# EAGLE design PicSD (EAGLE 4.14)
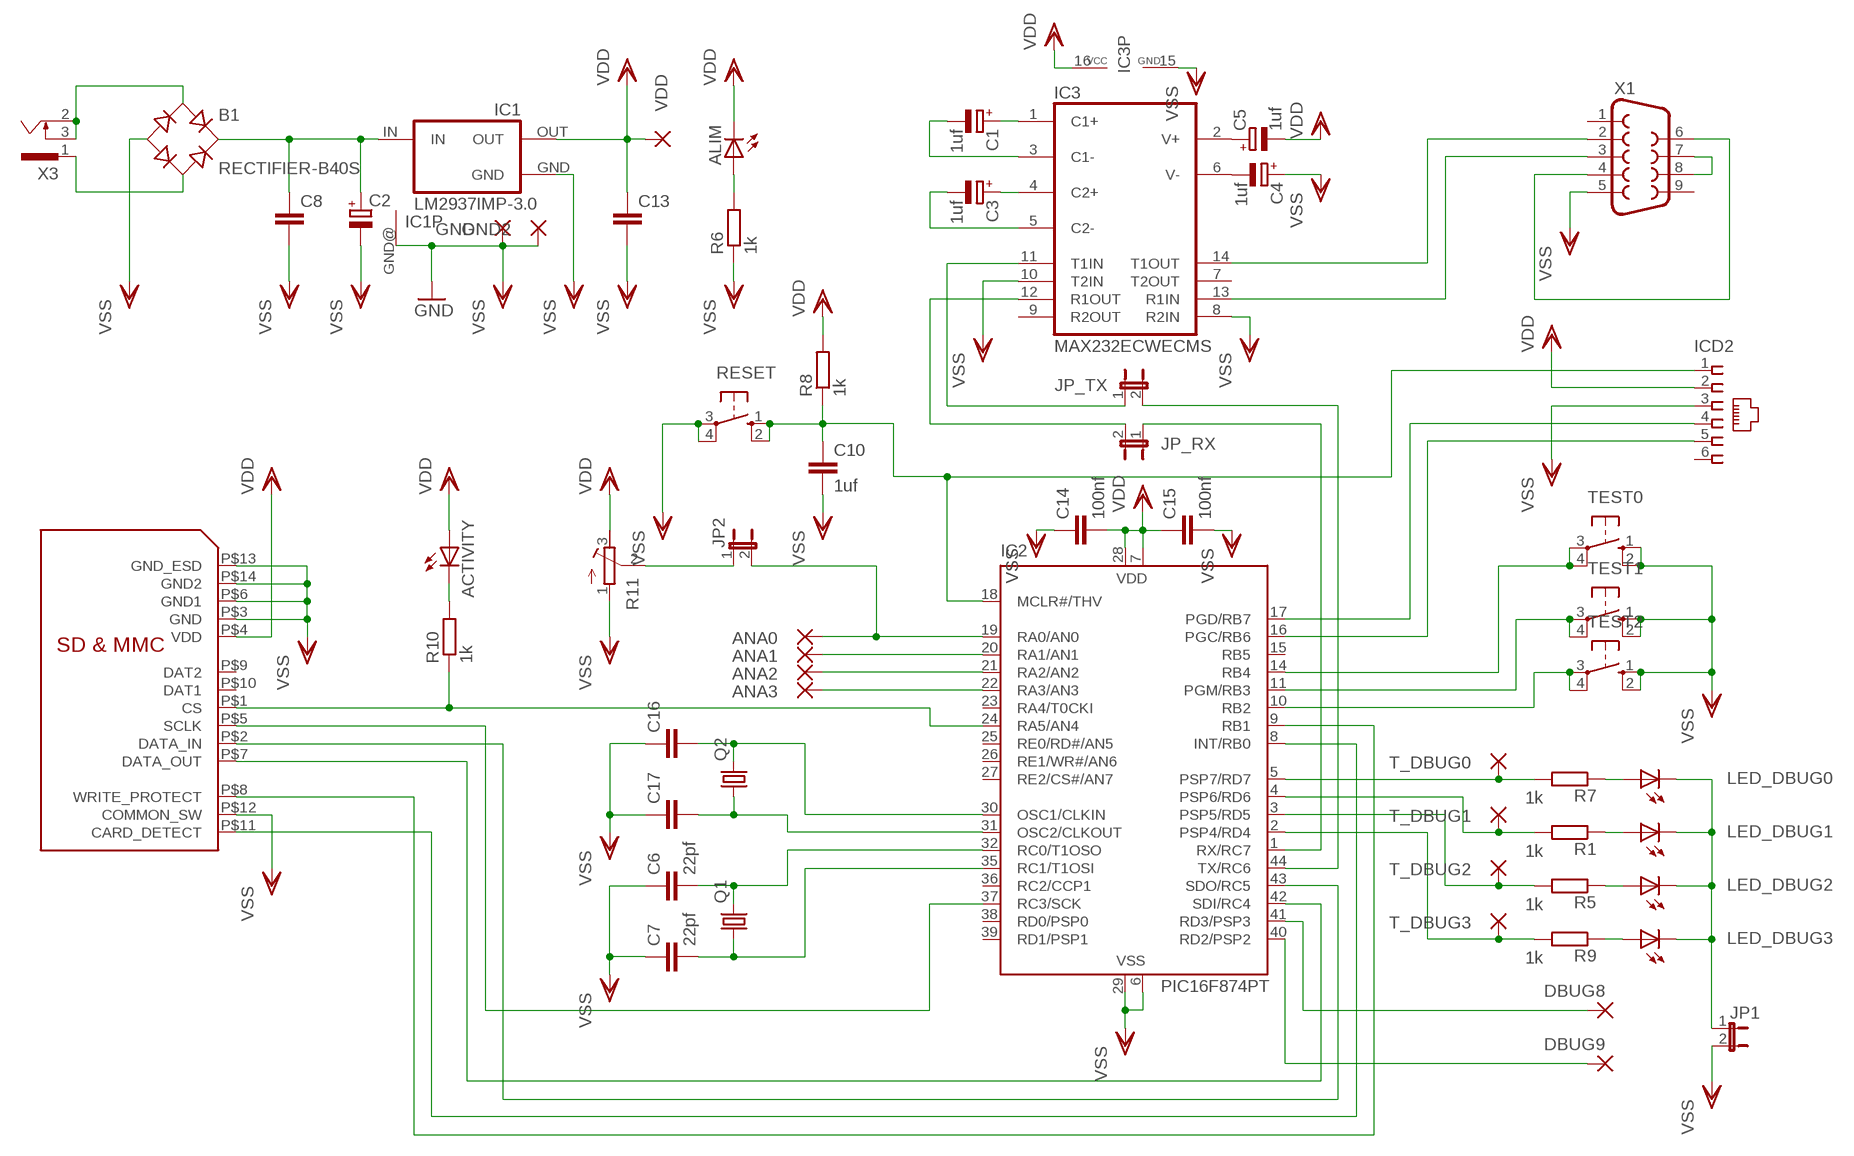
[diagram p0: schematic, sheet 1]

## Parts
ACTIVITY  LEDSMT1206  [1206]
ALIM  LEDSMT1206  [1206]
ANA0  3,81/1,1  [3,81/1,1]
ANA1  3,81/1,1  [3,81/1,1]
ANA2  3,81/1,1  [3,81/1,1]
ANA3  3,81/1,1  [3,81/1,1]
B1  RECTIFIER-B40S  [B40S]
C1  1uf  CPOL-EUB  [PANASONIC_B]
C2  CPOL-EUB  [PANASONIC_B]
C3  1uf  CPOL-EUB  [PANASONIC_B]
C4  1uf  CPOL-EUB  [PANASONIC_B]
C5  1uf  CPOL-EUB  [PANASONIC_B]
C6  22pf  C-EUC0805  [C0805]
C7  22pf  C-EUC0805  [C0805]
C8  C-EUC0805  [C0805]
C10  1uf  C-EUC0805  [C0805]
C13  C-EUC0805  [C0805]
C14  100nf  C-EUC0805  [C0805]
C15  100nf  C-EUC0805  [C0805]
C16  C-EUC0805  [C0805]
C17  C-EUC0805  [C0805]
DBUG8  3,81/1,1  [3,81/1,1]
DBUG9  3,81/1,1  [3,81/1,1]
GND  3,81/1,1  [3,81/1,1]
GND2  3,81/1,1  [3,81/1,1]
IC1  LM2937IMP-3.0  LM2937IMP-5.0  [SOT223]
IC2  PIC16F874PT  [TQFP44]
IC3  MAX232ECWECMS  [SO16]
ICD2  520250-3  [520250-3]
JP1  JP1E  [JP1]
JP2  JP1E  [JP1]
JP_RX  JP1E  [JP1]
JP_TX  JP1E  [JP1]
LED_DBUG0  LEDSMT1206  [1206]
LED_DBUG1  LEDSMT1206  [1206]
LED_DBUG2  LEDSMT1206  [1206]
LED_DBUG3  LEDSMT1206  [1206]
Q1  CRYTALTC26H  [TC26H]
Q2  CRYTALSM49  [SM49]
R1  1k  R-EU_R0805  [R0805]
R5  1k  R-EU_R0805  [R0805]
R6  1k  R-EU_R0805  [R0805]
R7  1k  R-EU_R0805  [R0805]
R8  1k  R-EU_R0805  [R0805]
R9  1k  R-EU_R0805  [R0805]
R10  1k  R-EU_R0805  [R0805]
R11  R-TRIMM3339P  [RTRIM3339P]
RESET  10-XX  [B3F-10XX]
SD1  FPS009-2405-0  FPS009-2405-0"  [FPS009-2405]
T_DBUG0  3,81/1,1  [3,81/1,1]
T_DBUG1  3,81/1,1  [3,81/1,1]
T_DBUG2  3,81/1,1  [3,81/1,1]
T_DBUG3  3,81/1,1  [3,81/1,1]
TEST0  10-XX  [B3F-10XX]
TEST1  10-XX  [B3F-10XX]
TEST2  10-XX  [B3F-10XX]
VDD  3,81/1,1  [3,81/1,1]
X1  F09H  [F09H]
X3  SCD-014A  [SCD-014-A]

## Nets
-SS: IC2.24(RA5/AN4) R10.1 SD1.P$1(CS)
N$1: C5.+ IC3.2(V+)
N$2: C4.- IC3.6(V-)
N$3: ALIM.A R6.2
N$4: ACTIVITY.C R10.2
N$5: IC2.9(RB1) SD1.P$8(WRITE_PROTECT)
N$7: ANA0.1(P) IC2.19(RA0/AN0) JP2.2
N$8: ANA1.1(P) IC2.20(RA1/AN1)
N$10: ANA2.1(P) IC2.21(RA2/AN2)
N$11: ANA3.1(P) IC2.22(RA3/AN3)
N$12: IC2.11(PGM/RB3) TEST1.3(P) TEST1.4(P1)
N$13: IC2.8(INT/RB0) SD1.P$11(CARD_DETECT)
N$14: IC2.10(RB2) TEST2.3(P) TEST2.4(P1)
N$15: IC2.14(RB4) TEST0.3(P) TEST0.4(P1)
N$16: IC2.5(PSP7/RD7) R7.2 T_DBUG0.1(P)
N$17: IC2.4(PSP6/RD6) R1.2 T_DBUG1.1(P)
N$18: IC2.3(PSP5/RD5) R5.2 T_DBUG2.1(P)
N$19: LED_DBUG0.A R7.1
N$20: LED_DBUG1.A R1.1
N$21: LED_DBUG2.A R5.1
N$22: C16.2 IC2.30(OSC1/CLKIN) Q2.2
N$24: DBUG8.1(P) IC2.41(RD3/PSP3)
N$25: C1.+ IC3.1(C1+)
N$26: C10.1 IC2.18(MCLR#/THV) ICD2.1 R8.1 RESET.1(S) RESET.2(S1)
N$27: DBUG9.1(P) IC2.40(RD2/PSP2)
N$28: C6.2 IC2.32(RC0/T1OSO) Q1.2
N$29: C7.2 IC2.35(RC1/T1OSI) Q1.1
N$30: B1.+ C2.+ C8.1 IC1.IN
N$31: B1.AC1 X3.2 X3.3
N$32: B1.AC2 X3.1
N$33: X1.7 X1.8
N$34: JP1.1 LED_DBUG0.C LED_DBUG1.C LED_DBUG2.C LED_DBUG3.C
N$35: LED_DBUG3.A R9.1
N$36: C1.- IC3.3(C1-)
N$37: C3.- IC3.5(C2-)
N$38: IC2.2(PSP4/RD4) R9.2 T_DBUG3.1(P)
N$39: C3.+ IC3.4(C2+)
N$41: JP2.1 R11.2(S)
N$42: IC3.14(T1OUT) X1.2
N$44: IC3.13(R1IN) X1.3
N$45: X1.4 X1.6
N$51: IC3.12(R1OUT) JP_RX.2
N$52: IC3.11(T1IN) JP_TX.1
N$69: C17.2 IC2.31(OSC2/CLKOUT) Q2.1
RB6: IC2.16(PGC/RB6) ICD2.5
RB7: IC2.17(PGD/RB7) ICD2.4
RC6: IC2.44(TX/RC6) JP_TX.2
RC7: IC2.1(RX/RC7) JP_RX.1
SCK: IC2.37(RC3/SCK) SD1.P$5(SCLK)
SDI: IC2.42(SDI/RC4) SD1.P$7(DATA_OUT)
SDO: IC2.43(SDO/RC5) SD1.P$2(DATA_IN)
VDD: ACTIVITY.A ALIM.C C5.- C13.1 C14.2 C15.1 IC1.OUT IC2.7(VDD) IC2.28(VDD) IC3.16(VCC) ICD2.2 R8.2 R11.3(A) SD1.P$4(VDD) VDD.1(P)
VSS: B1.- C2.- C4.+ C6.1 C7.1 C8.2 C10.2 C13.2 C14.1 C15.2 C16.1 C17.1 GND2.1(P) GND.1(P) IC1.GND IC1.GND@(GND) IC2.6(VSS) IC2.29(VSS) IC3.8(R2IN) IC3.10(T2IN) IC3.15(GND) ICD2.3 JP1.2 R6.1 R11.1(E) RESET.3(P) RESET.4(P1) SD1.P$3(GND) SD1.P$6(GND1) SD1.P$12(COMMON_SW) SD1.P$13(GND_ESD) SD1.P$14(GND2) TEST0.1(S) TEST0.2(S1) TEST1.1(S) TEST1.2(S1) TEST2.1(S) TEST2.2(S1) X1.5 ; supply symbol labelled GND
Unconnected: IC2.15(RB5) IC2.23(RA4/T0CKI) IC2.25(RE0/RD#/AN5) IC2.26(RE1/WR#/AN6) IC2.27(RE2/CS#/AN7) IC2.36(RC2/CCP1) IC2.38(RD0/PSP0) IC2.39(RD1/PSP1) IC3.7(T2OUT) IC3.9(R2OUT) ICD2.6 SD1.P$9(DAT2) SD1.P$10(DAT1) X1.1 X1.9

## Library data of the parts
ACTIVITY ALIM LED_DBUG0 LED_DBUG1-LED_DBUG3 = led:LED: LED
ANA0 ANA1-ANA3 DBUG8 DBUG9 GND GND2 T_DBUG0 T_DBUG1-T_DBUG3 VDD = wirepad:3,81/1,1: THROUGH-HOLE PAD
B1 = rectifier:RECTIFIER-: Rectifier
C1-C5 = rcl:CPOL-EU: POLARIZED CAPACITOR, European symbol
C6-C8 C10 C13-C17 = rcl:C-EU: CAPACITOR, European symbol
IC1 = lm2937:LM2937IMP-*: 400 and 500 mA Low Dropout Voltage Regulator NATIONAL SEMICONDUCTOR created by Peter.Hofmann@ph-tronic.de 10-2004 Rev.0
IC2 = microchip:PIC16F87*: MICROCONTROLLER
IC3 = maxim:MAX232ECWE: RS232 TRANSEIVER
ICD2 = con-amp:520250-3: AMP connector
JP1 JP2 JP_RX JP_TX = jumper:JP1E: JUMPER
Q1 Q2 = crystal:CRYTAL: CRYSTAL
R1 R5-R10 = rcl:R-EU_: RESISTOR, European symbol
R11 = rcl:R-TRIMM: Trimm resistor
RESET TEST0 TEST1 TEST2 = switch-omron:10-XX: OMRON SWITCH
SD1 = con-yamaichi-sd:FPS009-2405-0
X1 = con-subd:F09: SUB-D
X3 = con-shiua-chyuan:SCD-014A: Power Jack 2.5mm

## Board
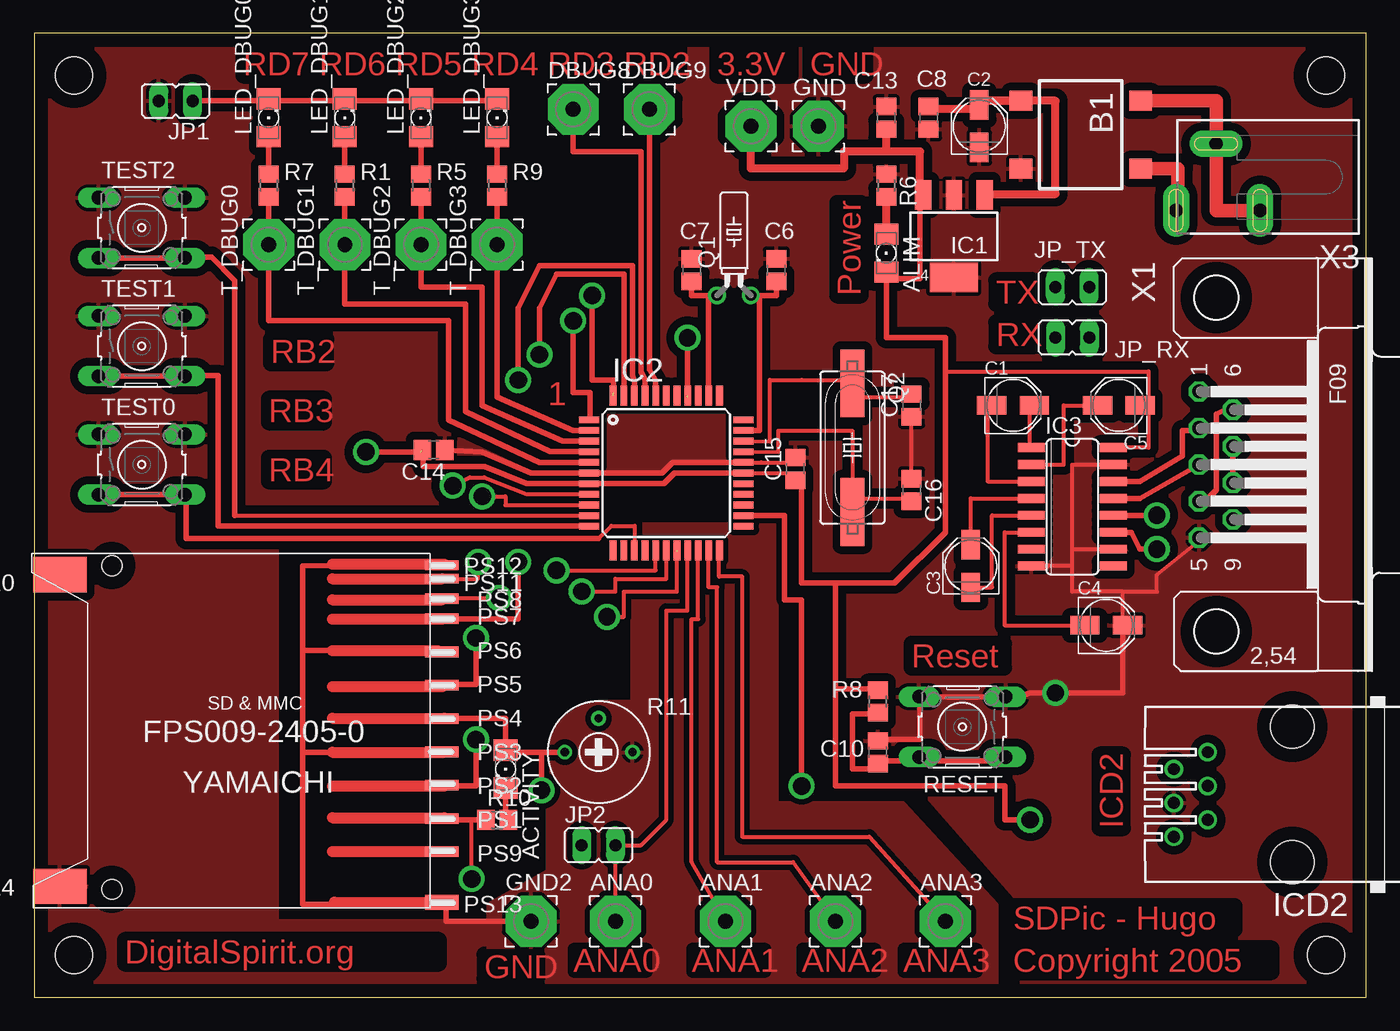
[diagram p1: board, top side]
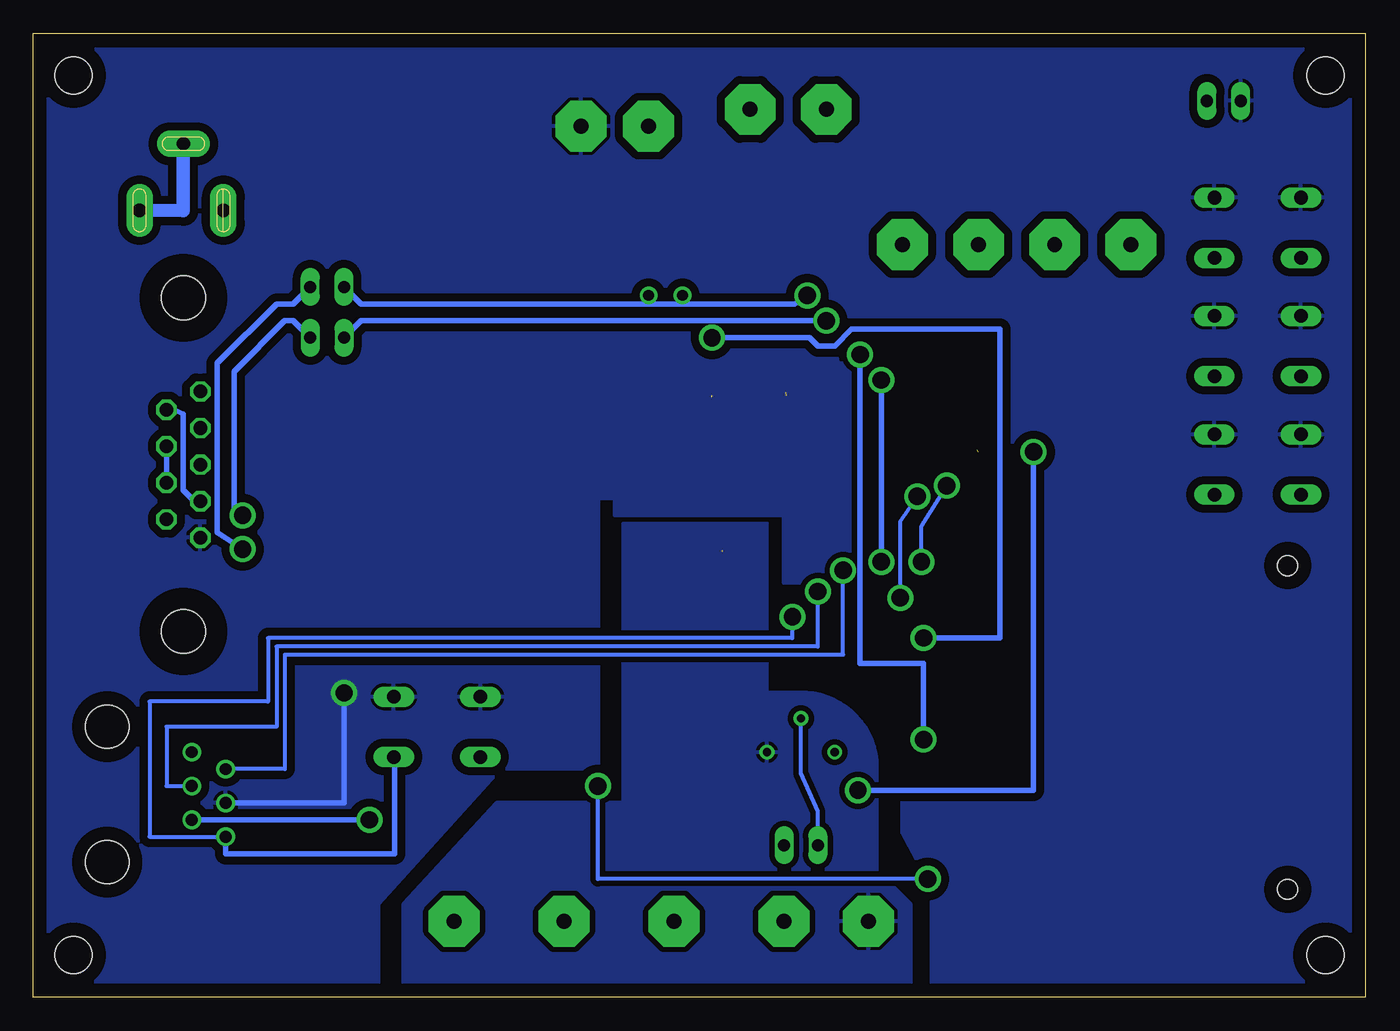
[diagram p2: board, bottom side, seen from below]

Size 100 x 72.38 mm. Coordinates in mm from the lower left corner, seen from the top.
Outline: 0,0 100,0 100,72.38 0,72.38 0,0
Copper layers (1*16): Top 0.035mm / dielectric 1.5mm / Bottom 0.035mm
Design rules "default": minimum track width 10mil, minimum drill 24mil, track to track 8mil, track to pad 8mil, pad to pad 8mil, via to via 8mil, smd to smd 8mil, copper to edge 40mil, drill to drill 8mil, minimum pad ring 10mil, minimum via ring 8mil, stop-mask expansion 4mil, vias tented up to drill 0mil, thermal gap 10mil
Holes 2.8 mm at 3.01,69.21 3.01,3.17 96.99,3.17 96.99,69.21

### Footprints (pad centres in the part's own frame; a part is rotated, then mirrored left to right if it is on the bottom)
1206 = smd 1.6 x 1.803: A -1.422,0; C 1.422,0
3,81/1,1 = drill 1.118 pad 3.81 octagon: 1 0,0
B40S = smd 1.5 x 1.7: + -2.55,-4.5; - 2.55,-4.5; AC1 -2.55,4.5; AC2 2.55,4.5
PANASONIC_B = smd 2.2 x 1.4: + 1.6,0; - -1.6,0
C0805 = smd 1.3 x 1.5: 1 -0.85,0; 2 0.85,0
SOT223 = smd 1.219 x 2.235: GND 0,-3.099; IN -2.311,-3.099; OUT 2.311,-3.099 | smd 3.6 x 2.2: GND@ 0,3.099
TQFP44 = smd 1.5 x 0.5: 1 -5.8,4; 2 -5.8,3.2; 3 -5.8,2.4; 4 -5.8,1.6; 5 -5.8,0.8; 6 -5.8,0; 7 -5.8,-0.8; 8 -5.8,-1.6; 9 -5.8,-2.4; 10 -5.8,-3.2; 11 -5.8,-4; 23 5.8,-4; 24 5.8,-3.2; 25 5.8,-2.4; 26 5.8,-1.6; 27 5.8,-0.8; 28 5.8,0; 29 5.8,0.8; 30 5.8,1.6; 31 5.8,2.4; 32 5.8,3.2; 33 5.8,4 | smd 0.5 x 1.5: 12 -4,-5.8; 13 -3.2,-5.8; 14 -2.4,-5.8; 15 -1.6,-5.8; 16 -0.8,-5.8; 17 0,-5.8; 18 0.8,-5.8; 19 1.6,-5.8; 20 2.4,-5.8; 21 3.2,-5.8; 22 4,-5.8; 34 4,5.8; 35 3.2,5.8; 36 2.4,5.8; 37 1.6,5.8; 38 0.8,5.8; 39 0,5.8; 40 -0.8,5.8; 41 -1.6,5.8; 42 -2.4,5.8; 43 -3.2,5.8; 44 -4,5.8
SO16 = smd 0.66 x 2.032: 1 -4.445,-3.073; 2 -3.175,-3.073; 3 -1.905,-3.073; 4 -0.635,-3.073; 5 0.635,-3.073; 6 1.905,-3.073; 7 3.175,-3.073; 8 4.445,-3.073; 9 4.445,3.073; 10 3.175,3.073; 11 1.905,3.073; 12 0.635,3.073; 13 -0.635,3.073; 14 -1.905,3.073; 15 -3.175,3.073; 16 -4.445,3.073
520250-3 = drill 0.889 round: 1 -3.175,8.89; 2 -1.905,6.35; 3 -0.635,8.89; 4 0.635,6.35; 5 1.905,8.89; 6 3.175,6.35 | hole 3.251: -5.08,0; 5.08,0
JP1 = drill 0.914 long: 1 0,-1.27; 2 0,1.27
TC26H = drill 0.813 round: 1 -1.27,0; 2 1.27,0
SM49 = smd 5.08 x 1.778: 1 -4.826,0; 2 4.826,0
R0805 = smd 1.3 x 1.5: 1 -0.85,0; 2 0.85,0
RTRIM3339P = drill 0.61 round: 1 -2.54,0; 2 0,-2.54; 3 2.54,0
B3F-10XX = drill 1.016 long: 1 -3.251,2.261; 2 3.251,2.261; 3 -3.251,-2.261; 4 3.251,-2.261
FPS009-2405 = smd 2.5 x 0.8: P$1 -14.27,6.88; P$2 -14.27,4.38; P$3 -14.27,1.88; P$4 -14.27,-0.62; P$5 -14.27,-3.12; P$6 -14.27,-5.62; P$7 -14.27,-8.12; P$8 -14.27,-9.62; P$9 -14.27,9.38 | smd 4 x 2.65: P$10 14.4,-11.42; P$14 14.4,11.98 | smd 2.5 x 0.7: P$11 -14.27,-11.12; P$12 -14.27,-12.12 | smd 2.5 x 1.1: P$13 -14.27,13.18 | hole 1.5: 10.5,12.2; 10.5,-12.1
F09H = drill 1.016 octagon: 1 -5.486,-1.27; 2 -2.743,-1.27; 3 0,-1.27; 4 2.743,-1.27; 5 5.486,-1.27; 6 -4.115,1.27; 7 -1.372,1.27; 8 1.372,1.27; 9 4.115,1.27 | hole 3.302: -12.522,0; 12.522,0
SCD-014-A = drill 1 pad 2 long: 1 -2.5,13.8; 2 -2.5,7.5; 3 2.5,10.8

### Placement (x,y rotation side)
ACTIVITY  35.39,17.14 270 top
ALIM  63.97,55.88 270 top
ANA0  43.65,5.71 0 top
ANA1  51.91,5.71 0 top
ANA2  60.16,5.71 0 top
ANA3  68.41,5.71 0 top
B1  78.58,64.77 270 top
C1  73.5,44.45 0 top
C2  70.95,65.4 90 top
C3  70.32,32.38 90 top
C4  80.48,27.93 0 top
C5  81.43,44.45 180 top
C6  55.71,54.61 270 top
C7  49.37,54.61 270 top
C8  67.14,66.03 270 top
C10  63.34,18.41 90 top
C13  63.97,66.03 90 top
C14  30,41.11 180 top
C15  57.14,39.68 90 top
C16  65.88,38.1 270 top
C17  65.88,44.45 90 top
DBUG8  40.48,66.67 0 top
DBUG9  46.19,66.67 0 top
GND  58.89,65.4 0 top
GND2  37.3,5.71 0 top
IC1  69.05,57.15 180 top
IC2  47.46,39.37 0 top
IC3  77.94,36.83 270 top
ICD2  94.45,15.24 90 top
JP1  10.63,67.3 90 top
JP2  42.38,11.43 270 top
JP_RX  77.94,49.53 270 top
JP_TX  77.94,53.34 90 top
LED_DBUG0  17.61,66.03 90 top
LED_DBUG1  23.33,66.03 90 top
LED_DBUG2  29.04,66.03 90 top
LED_DBUG3  34.76,66.03 90 top
Q1  52.54,52.7 0 top
Q2  61.43,41.27 270 top
R1  23.33,60.96 270 top
R5  29.04,60.96 270 top
R6  63.97,60.96 270 top
R7  17.61,60.96 270 top
R8  63.34,22.22 90 top
R9  34.76,60.96 270 top
R10  34.76,13.33 0 top
R11  42.38,18.41 180 top
RESET  69.69,20.31 180 top
SD1  16.34,20.31 180 top
T_DBUG0  17.61,56.51 0 top
T_DBUG1  23.33,56.51 0 top
T_DBUG2  29.04,56.51 0 top
T_DBUG3  34.76,56.51 0 top
TEST0  8.09,40 0 top
TEST1  8.09,48.89 0 top
TEST2  8.09,57.78 0 top
VDD  53.81,65.4 0 top
X1  88.73,40 270 top
X3  99.53,61.59 90 top

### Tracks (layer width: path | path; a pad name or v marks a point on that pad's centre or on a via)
-SS  (via drill 1.3)
  Top 0.305: v32.85,8.89 32.85,13.33
  Top 0.406: SD1.P$1 30.84,13.44 30.95,13.33 32.85,13.33 R10.1 34.12,13.33 | v57.62,15.87 57.62,29.84 56.35,29.84 56.35,36.19 53.17,36.19 IC2.24
  Bottom 0.305: v57.62,15.87 57.62,8.89 v32.85,8.89
N$1
  Top 0.305: IC3.2 77.3,40 77.3,44.45 79.84,44.45
  Top 0.61: 79.84,44.45 C5.+
N$2
  Top 0.305: IC3.6 72.86,34.92 72.86,27.93 78.89,27.93
  Top 0.61: C4.- 78.89,27.93 79.21,27.93
N$3
  Top 0.61: 63.97,57.15 ALIM.A R6.2
N$4
  Top 0.406: 34.76,15.87 ACTIVITY.C 35.39,13.33 R10.2
N$5  (via drill 1.3)
  Top 0.305: IC2.9 35.39,36.97 35.39,37.62 v33.65,37.62 | SD1.P$8 30.61,29.98 30.63,30 v34.92,30
  Bottom 0.305: v34.92,30 34.92,35.71 v33.65,37.62
N$7
  Top 0.305: ANA0.1 JP2.2 45.55,11.43 47.46,13.33 47.46,29.05 49.05,29.05 49.05,33.49 49.06,33.5 IC2.19
N$8
  Top 0.305: ANA1.1 49.37,10.16 49.37,28.41 49.84,28.41 49.84,33.33 49.86,33.35 IC2.20
N$10
  Top 0.305: ANA2.1 56.98,10.16 51.27,10.16 51.27,30.79 50.63,30.79 50.63,33.49 50.66,33.52 IC2.21
N$11
  Top 0.305: ANA3.1 62.7,12.06 53.17,12.06 53.17,31.59 51.43,31.59 51.43,33.49 51.46,33.52 IC2.22 51.5,33.57
N$12
  Top 0.406: TEST1.3 10.99,46.63 11.27,46.35 11.34,46.43 TEST1.4 11.54,46.63 11.58,46.67 13.81,46.67 13.81,35.4 33.17,35.4 35.55,35.4 41.59,35.4 41.59,35.37 IC2.11
N$13  (via drill 1.3)
  Top 0.305: v31.43,38.41 32.7,39.05 33.81,39.05 36.98,37.78 42.06,37.78 | v33.33,32.7 33.33,31.43 30.63,31.43 arc314 SD1.P$11
  Top 0.406: 42.06,37.78 IC2.8
  Bottom 0.305: v33.33,32.7 33.33,35.4 v31.43,38.41
N$14
  Top 0.305: 15.08,36.19 41.59,36.19
  Top 0.406: TEST2.3 10.99,55.52 11.27,55.24 11.34,55.32 TEST2.4 11.54,55.52 11.58,55.56 13.33,55.56 15.08,53.81 15.08,36.19 | 41.59,36.19 41.59,36.16 IC2.10
N$15
  Top 0.305: IC2.14 45.06,35.38 45.08,35.4 43.33,35.4 42.38,34.44
  Top 0.406: TEST0.3 11.23,37.74 11.27,37.78 11.3,37.74 TEST0.4 11.39,37.74 11.42,37.78 11.42,34.44 42.38,34.44
N$16
  Top 0.406: R7.2 T_DBUG0.1 17.61,50.8 31.11,50.8 31.11,43.33 37.93,40.16 IC2.5
N$17
  Top 0.406: R1.2 T_DBUG1.1 23.33,52.07 32.38,52.07 32.38,43.97 38.74,40.97 41.57,40.97 41.59,40.95 41.6,40.97 IC2.4
N$18
  Top 0.406: R5.2 T_DBUG2.1 29.04,53.34 33.65,53.34 33.65,44.45 39.66,41.77 IC2.3
N$19
  Top 0.406: R7.1 LED_DBUG0.A
N$20
  Top 0.406: R1.1 LED_DBUG1.A
N$21
  Top 0.406: 29.68,64.77 LED_DBUG2.A R5.1
N$22
  Top 0.305: IC2.30 55.87,40.95 55.87,42.54 61.43,42.54 61.43,37.46 | 61.43,36.19 Q2.2 61.43,37.46 | C16.2 65.88,37.46 61.43,37.46
N$23
  pour Bottom (isolate 0.406): 38.57,47.62 38.57,31.11 43.65,31.11 43.65,36.19 56.35,36.19 56.35,47.62
N$24
  Top 0.406: DBUG8.1 40.48,63.5 45.55,63.5 45.55,46.98 45.87,46.35 45.87,45.24 IC2.41 45.87,45.4
N$25
  Top 0.305: IC3.1 74.77,41.27 74.77,44.45
  Top 0.61: 74.77,44.45 C1.+
N$26  (via drill 1.3)  (1 unrouted)
  Top 0.305: 48.25,33.49 48.25,30.47 44.28,30.47 44.28,28.57 v43.02,28.57
  Top 0.406: RESET.1 72.94,17.85 72.86,17.77 66.51,17.77 | 63.34,17.14 C10.1 | 63.34,17.14 61.43,17.14 61.43,21.27 63.34,21.27 R8.1 | 63.34,17.14 63.34,17.77 66.51,17.77 | 66.51,17.77 arc-149 RESET.2
  Bottom 0.305: v43.02,28.57 43.02,26.98 82.39,26.98 82.39,22.22 91.28,22.22 91.28,12.06 ICD2.1
  Bottom 0.406: RESET.1 73.5,17.77 72.86,17.77 72.86,10.79 85.56,10.79 ICD2.1
N$27
  Top 0.406: DBUG9.1 46.19,47.14 46.67,46.35 46.67,45.4 IC2.40
N$28
  Top 0.406: 54.45,52.7 Q1.2 | 54.45,52.7 55.71,52.7 C6.2 55.71,53.97 | IC2.32 54.45,42.54 54.45,52.7
N$29
  Top 0.406: 49.37,53.97 C7.2 49.37,52.7 50.63,52.7 | 50.63,52.7 Q1.1 | IC2.35 50.63,45.08 50.63,52.7
N$30
  Top 0.61: 70.95,67.3 B1.+ | C8.1 67.14,66.67 70.95,66.67 C2.+ 70.95,67.3 | 70.95,67.3 76.67,67.3 76.67,60.32 71.59,60.32 IC1.IN
N$31
  Top 1.016: B1.AC1 88.73,67.3 88.73,59.05 91.91,59.05 X3.2
  Bottom 1.016: X3.2 88.73,59.05 88.73,64.13 X3.3
N$32
  Top 1.016: B1.AC2 85.88,62.23 85.88,59.37 X3.1
N$33
  Top 0.406: X1.8 X1.7
N$34
  Top 0.406: LED_DBUG3.C 34.76,67.3 29.04,67.3 | 29.04,67.3 LED_DBUG2.C | 22.7,67.3 29.04,67.3 | 22.7,67.3 LED_DBUG1.C | 17.61,67.3 22.7,67.3 | 17.61,67.3 LED_DBUG0.C | JP1.1 17.61,67.3
N$35
  Top 0.406: 34.76,64.77 LED_DBUG3.A R9.1
N$36
  Top 0.305: C1.- 71.59,44.45 71.59,38.73 IC3.3
  Top 0.61: C1.-
N$37
  Top 0.305: IC3.5 71.91,36.19 71.91,30.79 70.32,30.79
  Top 0.61: C3.- 70.32,30.79 70.32,31.11
N$38
  Top 0.406: R9.2 T_DBUG3.1 34.76,45.08 40.48,42.54 41.74,42.54 41.72,42.57 IC2.2
N$39
  Top 0.305: IC3.4 70.32,37.46 C3.+
N$40
  Top 0.813: 22.38,10.95 30.63,10.95
N$41
  Bottom 0.305: JP2.1 41.11,13.97 42.38,16.82 R11.2
N$42
  Top 0.406: IC3.14 83.02,38.73 86.19,40.64 86.19,42.54 87.47,42.54 X1.2
  Top 0.61: X1.2 87.47,42.86
N$43
  Top 0.813: 22.38,13.49 30.79,13.49
N$44
  Top 0.406: IC3.13 83.02,37.46 X1.3
N$45
  Top 0.406: X1.6 90,44.45 88.73,43.81 88.73,38.1 87.47,36.83 X1.4
N$46
  Top 0.813: 22.38,15.87 30.79,15.87
N$47
  Top 0.813: 22.38,20.95 30.79,20.95
N$48
  Top 0.813: 22.54,7.14 30.63,7.14
N$49
  Top 0.813: 22.38,23.33 30.63,23.33
N$50
  Top 0.813: 22.38,28.41 30.63,28.41
N$51  (via drill 1.3)
  Top 0.406: IC3.12 v84.29,36.19
  Bottom 0.406: v84.29,36.19 84.92,36.19 84.92,46.98 81.11,50.8 80.48,50.8 JP_RX.2
N$52  (via drill 1.3)
  Top 0.406: IC3.11 82.39,34.92 83.02,33.65 v84.29,33.65
  Bottom 0.406: v84.29,33.65 86.19,34.92 86.19,47.62 81.75,52.07 80.48,52.07 JP_TX.1
N$53
  Top 0.813: 22.38,29.84 30.63,29.84
N$54
  Top 0.813: 22.38,31.43 30.63,31.43
N$55
  Top 0.813: 22.38,32.54 30.79,32.54
N$56
  Bottom 0.406: 90,38.73 90,41.27
N$57
  Bottom 0.406: 87.47,36.83 88.73,38.1 88.73,43.81 90,44.45
N$69
  Top 0.305: IC2.31 55.24,41.75 55.24,46.35 57.62,46.35 61.43,46.35 | C17.2 65.88,45.08 61.43,45.08 61.43,46.35 | 61.43,46.35 Q2.1
RB6  (via drill 1.3)
  Top 0.305: IC2.16 46.67,32.06 v39.2,32.06
  Bottom 0.305: v39.2,32.06 39.2,25.71 81.11,25.71 81.11,17.14 ICD2.5
RB7  (via drill 1.3)
  Top 0.305: IC2.17 47.46,31.43 43.65,31.43 43.65,30.47 v41.11,30.47
  Bottom 0.305: v41.11,30.47 41.11,26.35 81.75,26.35 81.75,20.31 90,20.31 90,15.87 ICD2.4
RC6  (via drill 1.3)  (1 unrouted)
  Top 0.406: 43.49,45.4 43.49,46.35 41.9,46.35 v41.9,52.7
  Bottom 0.406: JP_TX.2 75.4,52.07 42.86,52.07 v41.9,52.7
RC7  (via drill 1.3)
  Top 0.406: IC2.1 41.74,43.33 41.74,45.4 40.48,45.4 v40.48,50.8
  Bottom 0.406: JP_RX.1 75.4,50.8 v40.48,50.8 41.59,50.8
SCK  (via drill 1.3)  (1 unrouted)
  Top 0.406: SD1.P$5 30.95,23.49 33.17,23.49 v33.17,26.98 | v49.05,49.53 49.05,45.08
  Bottom 0.406: v33.17,26.98 27.46,26.98 27.46,50.16 38.57,50.16 39.84,48.89 41.11,48.89 41.74,49.53 v49.05,49.53
SDI  (via drill 1.3)
  Top 0.406: SD1.P$7 30.95,28.41 34.44,28.41 | 34.44,28.41 | v36.35,32.7 36.35,28.41 34.44,28.41 | v36.35,46.35 36.35,51.75 37.94,54.92 44.92,54.92 44.92,46.67 45.08,46.19 45.08,45.24 IC2.42
  Bottom 0.406: v36.35,32.7 v36.35,46.35
SDO  (via drill 1.3)
  Top 0.406: SD1.P$2 30.88,15.94 30.95,15.87 33.17,15.87 v33.17,19.36 | v37.94,48.26 37.94,51.75 39.2,54.29 44.28,54.29 44.28,45.4 IC2.43
  Bottom 0.406: v33.17,19.36 33.17,25.08 37.94,25.08 v37.94,48.26
VDD  (via drill 1.3)  (1 unrouted)
  Top 0.305: C15.1 56.98,39.37 53.33,39.37 | 81.11,41.27 83.66,41.27 83.66,44.45 | 83.66,44.45 83.66,46.98 68.41,46.98 | 83.66,44.45 83.34,44.45
  Top 0.406: 81.11,41.27 IC3.16 | IC2.28 53.33,39.37 48.09,39.37 47.3,38.57 47.14,38.57 IC2.7 37.46,38.57 36.98,38.57 33.81,39.84 29.2,39.84 29.2,41.43 C14.2 | v74.77,13.33 72.86,13.33 72.86,15.87 60.16,15.87 60.16,23.17 | R8.2 63.34,23.17 60.16,23.17 | 60.16,31.11 60.16,23.17 | 60.16,31.11 57.62,31.11 57.62,38.73 C15.1 | 63.97,53.97 ALIM.C | 63.97,53.97 66.51,53.97 66.51,60.32 IC1.OUT | 63.97,53.97 63.97,49.53 68.41,49.53 68.41,46.98 68.41,34.92 64.61,31.11 60.16,31.11 | SD1.P$4 30.95,20.95 35.39,20.95 ACTIVITY.A 35.39,18.41 38.09,18.41 | 38.09,18.41 R11.3 | v24.92,40.95 29.04,40.95 | v38.09,15.55 38.09,18.41
  Top 0.61: 83.34,44.45 C5.- | VDD.1 53.81,62.23 60.8,62.23 60.8,63.5 63.97,63.5 | 63.97,65.4 C13.1 63.97,63.5 | 63.97,63.5 66.51,63.5 66.51,60.32
  Bottom 0.406: v74.77,13.33 ICD2.2 | v24.92,40.95 24.92,41.11 24.92,15.55 26.82,15.55 v38.09,15.55
VSS  (via drill 1.3)
  Top 0.305: IC2.29 54.6,40.16 56.98,40.16 56.98,40.64 C15.2 | 65.88,43.81 C17.1 C16.1 | 77.94,32.38 76.03,32.38 | 81.11,40 IC3.15 77.94,40 77.94,33.65 | 77.94,32.38 77.94,33.65 | 77.94,33.65 81.11,33.65 | 77.94,32.38 74.77,32.38 | 77.94,32.38 77.94,30.47 81.75,30.47 | 87.47,34.29 84.29,31.74 84.29,30.47 81.75,30.47 | 81.75,27.93 81.75,30.47
  Top 0.406: 74.77,32.38 IC3.8 76.03,32.38 | 87.47,34.6 87.47,34.92 | 87.47,34.29 X1.5 | 82.39,27.93 C4.+ 81.75,27.93 81.75,22.86 v76.67,22.86 74.77,22.86 72.78,22.14 | 72.94,22.14 72.86,22.22 72.78,22.14 | 72.94,22.14 RESET.3 | 72.78,22.14 73.22,22.58 RESET.4 66.51,22.54 66.51,19.36 63.34,19.36 C10.2 | 72.78,22.14 72.94,22.14 | IC2.29 53.33,40.16 47.94,40.16 47.14,39.37 IC2.6 38.09,39.37 | 38.09,39.37 37.94,39.37 | C7.1 49.37,55.88 | C6.1 55.71,55.88 | 20.15,26.03 20.15,32.38 SD1.P$12 30.95,32.38 | SD1.P$6 30.95,26.03 30.31,26.03 | 20.15,26.03 22.38,26.03 | 20.15,18.41 20.15,26.03 | 20.15,18.41 22.38,18.41 | 30.79,18.41 30.95,18.41 SD1.P$3 20.15,18.41 | 20.15,18.41 20.15,6.98 30.95,6.98 | 30.95,6.98 SD1.P$13 30.95,7.13 30.95,6.98 | GND2.1 30.95,5.71 30.95,6.98 | C14.1 33.65,40.95 37.3,39.37 38.09,39.37
  Top 0.61: 81.11,33.65 IC3.10 | X1.5 87.47,34.6 | 70.95,64.13 C2.- 70.95,63.5 | C8.2 67.14,65.4 | C13.2 63.97,66.67 | R6.1 63.97,61.59 | IC1.GND@ 69.05,53.97
  Top 0.813: 22.38,18.41 30.79,18.41 | 22.38,26.03 30.31,26.03
  Bottom 0.406: ICD2.3 76.67,14.6 v76.67,22.86
  pour Top (isolate 0.406): 55.71,35.55 55.71,14.6 65.24,14.6 72.22,6.98 72.22,0.63 34.12,0.63 34.12,6.98 38.57,9.52 38.57,17.14 arc-90 42.38,22.22 44.92,22.22 44.92,35.55
  pour Bottom (isolate 0.406): 44.92,35.55 55.71,35.55 55.71,14.6 65.24,14.6 72.22,6.98 72.22,0.63 34.12,0.63 34.12,6.98 36.66,9.52 36.66,17.77 arc-90 43.02,22.86 44.92,22.86
  pour Top (isolate 0.61): 0.47,71.75 0.47,0.63 34.12,0.63 34.12,5.71 18.25,5.71 18.25,33.65 42.38,33.65 42.38,37.46 57.62,37.46 57.62,17.14 65.24,17.14 74.13,6.98 74.13,0.63 99.53,0.63 99.53,71.75
  pour Bottom (isolate 0.61): 0.47,71.75 0.47,0.63 32.54,0.63 32.54,8.25 34.76,12.38 34.76,22.54 41.11,24.76 42.38,24.76 42.38,37.46 57.62,37.46 57.62,17.14 64.92,17.14 74.13,6.98 74.13,0.63 99.53,0.63 99.53,71.75

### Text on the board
Top: RD7 | RD6 | RD5 | RD4 | RD3 | RD2 | 3.3V | GND | Power | TX | RX | RB2 | 1 | RB3 | RB4 | Reset | ICD2 | SDPic - Hugo | DigitalSpirit.org | GND | ANA0 | ANA1 | ANA2 | ANA3 | Copyright 2005
tDocu: Rev1 (hugo - 20/09/2005): Ajout Led "Activity", Ajout connection "Write Protect" | Rev2 (hugo - 21/10/2005): Correction sur le plan de masse et correction "Write Protect" de la SD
